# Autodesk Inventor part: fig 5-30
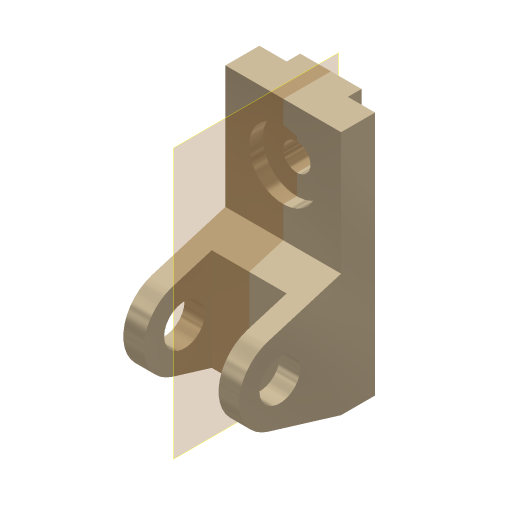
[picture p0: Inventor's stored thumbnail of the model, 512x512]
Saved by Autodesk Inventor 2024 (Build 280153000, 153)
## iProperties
Shininess: 65.0
Angle Display Precision: 2
Document Length Units: 11269
Document Angle Units: 11279
Document Time Units: 11290
Document Mass Units: 11283
Document Length Units Precision: 3
Document Angle Units Precision: 2
Created: 2001-11
Part Number: fig 5-30
Document SubType Name: Modeling
Designer: Renu Muthoo
Density: 1 g/cm^3
Material: Generic
Appearance: Metal-Titanium (Polished)
Density: 0.0
Volumn: 0.0
Area: 0.0
PropertySet Name: Model Information
Control State: 0
Master: False
Checked Out: False
Author: Renu Muthoo
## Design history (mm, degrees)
sketch "Sketch2"
  geometry: L1 (33.257, 104.664)-(33.257, -75.336); L2 (33.257, -75.336)-(8.257, -75.336); L3 (8.257, -75.336)-(-45.451, -59.045); L4 (-45.451, -1.628)-(8.257, 14.664); L5 (8.257, 14.664)-(8.257, 104.664); L6 (8.257, 104.664)-(33.257, 104.664); C1 r 15 at (-36.743, -30.336); A1 r 30 centre (-36.743, -30.336) between (-45.451, -1.628) and (-45.451, -59.045)
  constraints: 12 end point, 2 centre point, 2 equal length, 2 parallel, 2 point on circle, 2 tangent, 1 coincident, 1 perpendicular, 1 vertical
  dimensions: "d0" = 180 distance of L1.start L1.end; "d1" = 30 radius of A1; "d2" = 25 distance of L5.end L1.start; "d3" = 45 distance from line of L2 A1.centre; "d4" = 70 distance from line of L1 A1.centre; "d5" = 30 diameter of C1
extrude "Extrusion1" new body sketch "Sketch2" distance "d6" = 85; taper "d7" = 0 deg
workplane "Work Plane1"
sketch "Sketch3"
  geometry: L1 (15, 62.364)-(70, 62.364); L2 (70, 62.364)-(70, -52.386); L3 (70, -52.386)-(15, -52.386); L4 (15, -52.386)-(15, 62.364); L5 (0, -45)-(0, -28.708) reference
  constraints: 8 end point, 2 parallel, 1 horizontal, 1 perpendicular
  dimensions: "d8" = 55 distance of L1.start L1.end; "d9" = 15 distance between parallel lines of L5 L4
extrude "Extrusion2" cut sketch "Sketch3" distance "d10" = 50; taper "d11" = 0 deg
sketch "Sketch4"
  geometry: L1 (0, 25)-(85, 25) reference; L2 (0, 0)-(0, 25) reference; L3 (20, 25)-(65, 25); L4 (65, 25)-(65, 35); L5 (65, 35)-(20, 35); L6 (20, 35)-(20, 25)
  constraints: 8 end point, 2 parallel, 1 horizontal, 1 perpendicular, 1 point on line
  dimensions: "d12" = 45 distance of L4.end L5.end; "d13" = 10 distance of L3.end L4.end; "d14" = 20 distance between parallel lines of L2 L6
extrude "Extrusion3" join sketch "Sketch4" stored distance "d15" = 50; taper "d16" = 0 deg
sketch "Sketch5"
  geometry: L1 (85, 0)-(85, 90) reference; L2 (0, 90)-(85, 90) reference; 1 further point
  dimensions: "d17" = 42 distance from line of L2 point (42.5, 48); "d18" = 42.5 distance from line of L1 point (42.5, 48)
hole "Hole1" sketch "Sketch5" diameter "d19" = 20; stored, may be unused: countersink angle "d23" = 82 deg, drill point angle "d25" = 118 deg; dims "d20" = 6, "d21" = 50, "d22" = 10, "d24" = 8
workplane "Work Plane5"
body "Solid1"
node "Sketch1"
